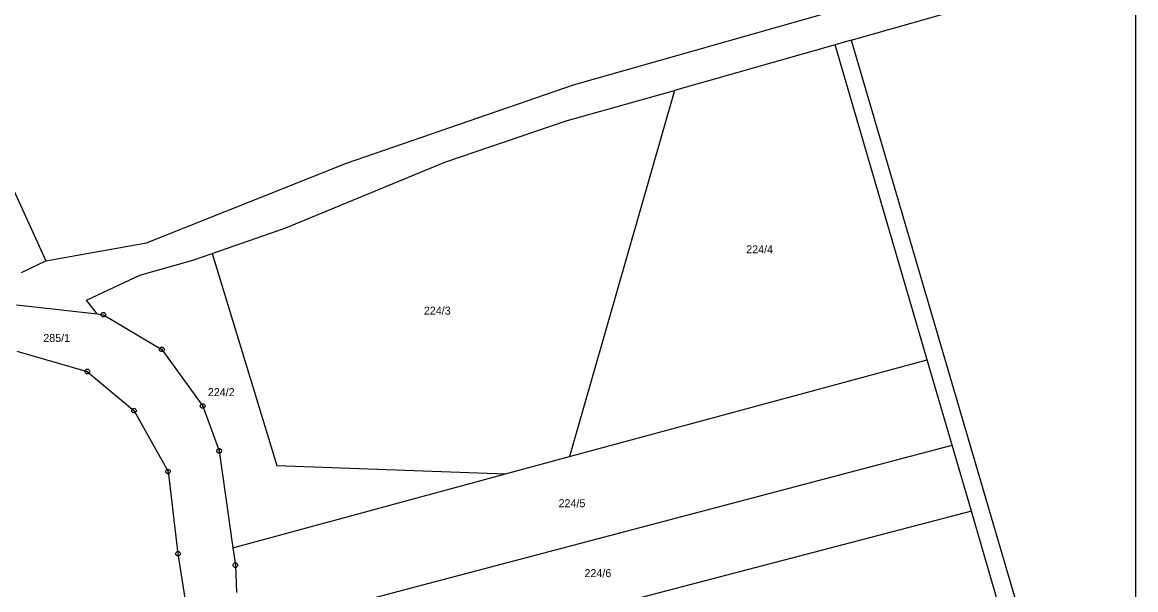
# Model space of a CAD drawing. Extents: x -780000 to -777378, y -1011169 to -1009297.
# Drawn here: x -778986.4 to -778750, y -1010240.1 to -1010119.6 of the extents above; entities that cross this region are included whole.
import ezdxf

# ---------------------------------------------------------------- set-up
doc = ezdxf.new("R2010")
doc.units = 0
for name, color, linetype in [('Default', 7, 'Continuous'), ('KLADY_ZMVM', 7, 'Continuous'), ('KN_HRANICE', 7, 'Continuous'), ('KN_PARCELY', 7, 'Continuous')]:
    doc.layers.add(name, color=color, linetype=linetype)

# ---------------------------------------------------------------- blocks, each defined once
blk = doc.blocks.new('105')
at = {"layer": 'Default'}
blk.add_line((-0.12, 0), (0.12, 0), dxfattribs=at)
blk.add_lwpolyline([(0.15, 0.48), (0.4, 0.3), (0.5, 0.01), (0.4, -0.28), (0.15, -0.46), (-0.16, -0.46), (-0.41, -0.28), (-0.51, 0.01), (-0.41, 0.3), (-0.16, 0.48), (0.15, 0.48)], dxfattribs=at)

msp = doc.modelspace()

# ---------------------------------------------------------------- linework, layer by layer
at = {"layer": 'KLADY_ZMVM'}
msp.add_lwpolyline([(-779108.78, -1010500), (-778750, -1010500), (-778750, -1010000)], dxfattribs=at)
at = {"layer": 'KN_HRANICE'}
for p, q in [((-778869.36, -1010132.88), (-778766.08, -1010103.5)), ((-778810.44, -1010123.41), (-778782.95, -1010115.6)), ((-778810.44, -1010123.41), (-778813.85, -1010124.38)), ((-778810.44, -1010123.41), (-778760.75, -1010292.49)), ((-778813.85, -1010124.38), (-778847.96, -1010134.1)), ((-778794.28, -1010191.27), (-778813.85, -1010124.38)), ((-778917.58, -1010149.52), (-778869.36, -1010132.88)), ((-778870.96, -1010140.49), (-778847.96, -1010134.1)), ((-778847.96, -1010134.1), (-778870.23, -1010211.82)), ((-778896.72, -1010149.28), (-778870.96, -1010140.49)), ((-778930.42, -1010163.26), (-778896.72, -1010149.28)), ((-778960.05, -1010166.44), (-778917.58, -1010149.52)), ((-778988.54, -1010154.56), (-778981.44, -1010170.24)), ((-778946.12, -1010168.67), (-778930.42, -1010163.26)), ((-778981.44, -1010170.24), (-778960.05, -1010166.44)), ((-778986.55, -1010172.74), (-778981.44, -1010170.24)), ((-778961.42, -1010173.29), (-778950.22, -1010170.08)), ((-778950.22, -1010170.08), (-778946.12, -1010168.67)), ((-778946.12, -1010168.67), (-778932.35, -1010213.67)), ((-778972.81, -1010178.62), (-778961.42, -1010173.29)), ((-778987.62, -1010179.6), (-778970.48, -1010181.53)), ((-778970.48, -1010181.53), (-778972.81, -1010178.62)), ((-778970.48, -1010181.53), (-778969.19, -1010181.68)), ((-778969.19, -1010181.68), (-778956.78, -1010189.07)), ((-778987.54, -1010189.4), (-778972.6, -1010193.75)), ((-778956.78, -1010189.07), (-778948.1, -1010201.08)), ((-778870.23, -1010211.82), (-778794.28, -1010191.27)), ((-778789, -1010209.36), (-778794.28, -1010191.27)), ((-778972.6, -1010193.75), (-778962.68, -1010202.09)), ((-778948.1, -1010201.08), (-778944.59, -1010210.6)), ((-778962.68, -1010202.09), (-778955.45, -1010215)), ((-778944.59, -1010210.6), (-778941.69, -1010231.16)), ((-778939.44, -1010249.05), (-778789, -1010209.36)), ((-778784.9, -1010223.38), (-778789, -1010209.36)), ((-778883.82, -1010215.5), (-778870.23, -1010211.82)), ((-778955.45, -1010215), (-778953.35, -1010232.46)), ((-778941.69, -1010231.16), (-778883.82, -1010215.5)), ((-778932.35, -1010213.67), (-778883.82, -1010215.5)), ((-778784.9, -1010223.38), (-778936.98, -1010263.15)), ((-778779.19, -1010242.93), (-778784.9, -1010223.38)), ((-778941.69, -1010231.16), (-778941.17, -1010234.88)), ((-778953.35, -1010232.46), (-778950.34, -1010251.89)), ((-778941.17, -1010234.88), (-778940.9, -1010240.67))]:
    msp.add_line(p, q, dxfattribs=at)

# ---------------------------------------------------------------- block references
at = {"layer": 'KN_PARCELY'}
for p in [(-778969.19, -1010181.68), (-778956.78, -1010189.07), (-778972.6, -1010193.75), (-778948.1, -1010201.08), (-778962.68, -1010202.09), (-778944.59, -1010210.6), (-778955.45, -1010215), (-778953.35, -1010232.46), (-778941.17, -1010234.88)]:
    msp.add_blockref('105', p, dxfattribs=at)

# ---------------------------------------------------------------- texts
for s, p in [('224/4', (-778832.7, -1010168.66)), ('224/3', (-778901.14, -1010181.67)), ('285/1', (-778981.95, -1010187.47)), ('224/2', (-778947.01, -1010198.98)), ('224/5', (-778872.54, -1010222.56)), ('224/6', (-778867.04, -1010237.41))]:
    msp.add_text(s, height=1.7, dxfattribs=at).set_placement(p)

doc.saveas('drawing.dxf')
